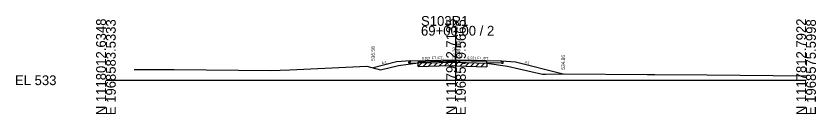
# Model space of a CAD drawing. Extents: x -26 to 203, y -10 to 12018.
# Drawn here: x -25.7 to 202.8, y 8490.3 to 8518.4 of the extents above; entities that cross this region are included whole.
import ezdxf

# ---------------------------------------------------------------- set-up
doc = ezdxf.new("R2010")
doc.units = 0
for name, color, linetype in [('Level 10', 7, 'Continuous'), ('Level 11', 7, 'Continuous'), ('Level 12', 7, 'Continuous'), ('Level 32', 7, 'Continuous'), ('Level 33', 7, 'Continuous'), ('Level 53', 7, 'Continuous'), ('Level 59', 7, 'Continuous'), ('Level 6', 7, 'Continuous'), ('Level 60', 7, 'Continuous'), ('Level 61', 7, 'Continuous'), ('Level 63', 7, 'Continuous'), ('Level 7', 7, 'Continuous')]:
    doc.layers.add(name, color=color, linetype=linetype)

msp = doc.modelspace()

# ---------------------------------------------------------------- linework, layer by layer
at = {"layer": 'Level 11'}
for p, q in [((86.5, 8505.27), (87, 8505.28)), ((86.5, 8504.91), (86.5, 8505.27)), ((87, 8504.92), (86.5, 8504.91)), ((87, 8505.28), (87, 8505.59)), ((113, 8505.28), (113, 8505.59)), ((113.5, 8505.27), (113, 8505.28)), ((113, 8504.92), (113.5, 8504.91)), ((113.5, 8504.91), (113.5, 8505.27))]:
    msp.add_line(p, q, dxfattribs=at)
at = {"layer": 'Level 12'}
for p, q in [((87, 8504.92), (89.19, 8504.96)), ((89.19, 8504.97), (89.19, 8504.96)), ((113, 8504.92), (108.78, 8505)), ((108.78, 8505), (108.78, 8504.87))]:
    msp.add_line(p, q, dxfattribs=at)
at = {"layer": 'Level 53'}
for p, q in [((89.19, 8505.32), (100, 8505.55)), ((89.19, 8504.97), (89.19, 8505.32)), ((108.78, 8505.36), (100, 8505.55)), ((108.78, 8504.87), (108.78, 8505.36))]:
    msp.add_line(p, q, dxfattribs=at)
at = {"layer": 'Level 59'}
for p, q in [((87, 8505.59), (100, 8505.86)), ((100, 8505.86), (113, 8505.59))]:
    msp.add_line(p, q, dxfattribs=at)
at = {"layer": 'Level 6'}
for p, q in [((87, 8505.59), (83, 8505.26)), ((113, 8505.59), (117, 8505.26))]:
    msp.add_line(p, q, dxfattribs=at)
at = {"layer": 'Level 60'}
for p, q in [((52.49, 8503), (74.5, 8504.04)), ((74.5, 8504.04), (78.45, 8503.02)), ((78.45, 8503.02), (83.58, 8504.2)), ((83.58, 8504.2), (89.19, 8504.97)), ((89.19, 8504.97), (95.2, 8505.11)), ((95.2, 8505.11), (98.99, 8505.2)), ((98.99, 8505.2), (100, 8505.17)), ((100, 8505.17), (108.78, 8504.87)), ((108.78, 8504.87), (114.7, 8504.01)), ((114.7, 8504.01), (124.7, 8501.72)), ((8.09, 8503.1), (14.92, 8503.07)), ((14.92, 8503.07), (19.53, 8503.06)), ((19.53, 8503.06), (47.05, 8502.78)), ((47.05, 8502.78), (52.49, 8503)), ((124.7, 8501.72), (125.57, 8501.74)), ((125.57, 8501.74), (130.91, 8501.86)), ((130.91, 8501.86), (154.62, 8501.67)), ((154.62, 8501.67), (156.81, 8501.66)), ((156.81, 8501.66), (171.72, 8501.51)), ((171.72, 8501.51), (200, 8501.28))]:
    msp.add_line(p, q, dxfattribs=at)
at = {"layer": 'Level 61'}
for p, q in [((89.19, 8503.97), (90.21, 8504.99)), ((89.19, 8503.97), (89.19, 8504.97)), ((89.19, 8503.97), (95.2, 8504.11)), ((90.69, 8504), (91.71, 8505.03)), ((92.19, 8504.04), (93.21, 8505.06)), ((93.69, 8504.07), (94.71, 8505.1)), ((95.19, 8504.11), (96.21, 8505.13)), ((95.2, 8504.11), (98.99, 8504.2)), ((96.69, 8504.14), (97.71, 8505.17)), ((98.19, 8504.18), (99.2, 8505.19)), ((98.99, 8504.2), (100, 8504.17)), ((99.69, 8504.18), (100.66, 8505.14)), ((100, 8504.17), (108.78, 8503.87)), ((101.19, 8504.12), (102.16, 8505.09)), ((102.69, 8504.07), (103.66, 8505.04)), ((104.19, 8504.02), (105.16, 8504.99)), ((105.69, 8503.97), (106.66, 8504.94)), ((107.19, 8503.92), (108.16, 8504.89)), ((108.78, 8504.87), (108.78, 8503.87))]:
    msp.add_line(p, q, dxfattribs=at)
at = {"layer": 'Level 63'}
for p, q in [((100, 8500), (100, 8515.6)), ((0, 8500), (100, 8500)), ((100, 8500), (200, 8500))]:
    msp.add_line(p, q, dxfattribs=at)
at = {"layer": 'Level 7'}
for p, q in [((83, 8505.26), (76.29, 8503.58)), ((117, 8505.26), (130.6, 8501.86))]:
    msp.add_line(p, q, dxfattribs=at)

# ---------------------------------------------------------------- texts
at = {"layer": 'Level 10'}
msp.add_text(' 538.23', height=0.9, rotation=90, dxfattribs=at).set_placement((99.95, 8505.31))
at = {"layer": 'Level 32'}
for s, rotation, p in [('0.021 FT./FT.', 1.1916, (90.21, 8505.91)), ('0.021 FT./FT.', 358.8084, (103.22, 8506.04)), ('4:1', 14.0362, (78.86, 8504.54)), ('4:1', 345.9638, (119.55, 8504.88))]:
    msp.add_text(s, height=0.75, rotation=rotation, dxfattribs=at).set_placement(p)
at = {"layer": 'Level 33'}
for s, p in [('536.58', (76.79, 8505.52)), ('534.86', (131.1, 8503.02))]:
    msp.add_text(s, height=1, rotation=90, dxfattribs=at).set_placement(p)
at = {"layer": 'Level 59'}
msp.add_text(' 538.86', height=1.2, rotation=90, dxfattribs=at).set_placement((101.2, 8505.86))
at = {"layer": 'Level 63'}
for s, p in [('N 1118012.6348', (0, 8490)), ('N 1117912.7135', (100, 8490)), ('N 1117812.7922', (200, 8490)), ('E 1968583.5333', (2.8, 8490)), ('E 1968579.5665', (102.8, 8490)), ('E 1968575.5998', (202.8, 8490))]:
    msp.add_text(s, height=2.8, rotation=90, dxfattribs=at).set_placement(p)
for s, p in [('S103R1', (90, 8515.6)), ('69+00.00 / 2', (90, 8512.8)), ('EL 533', (-26, 8498.6))]:
    msp.add_text(s, height=2.8, dxfattribs=at).set_placement(p)

doc.saveas('drawing.dxf')
